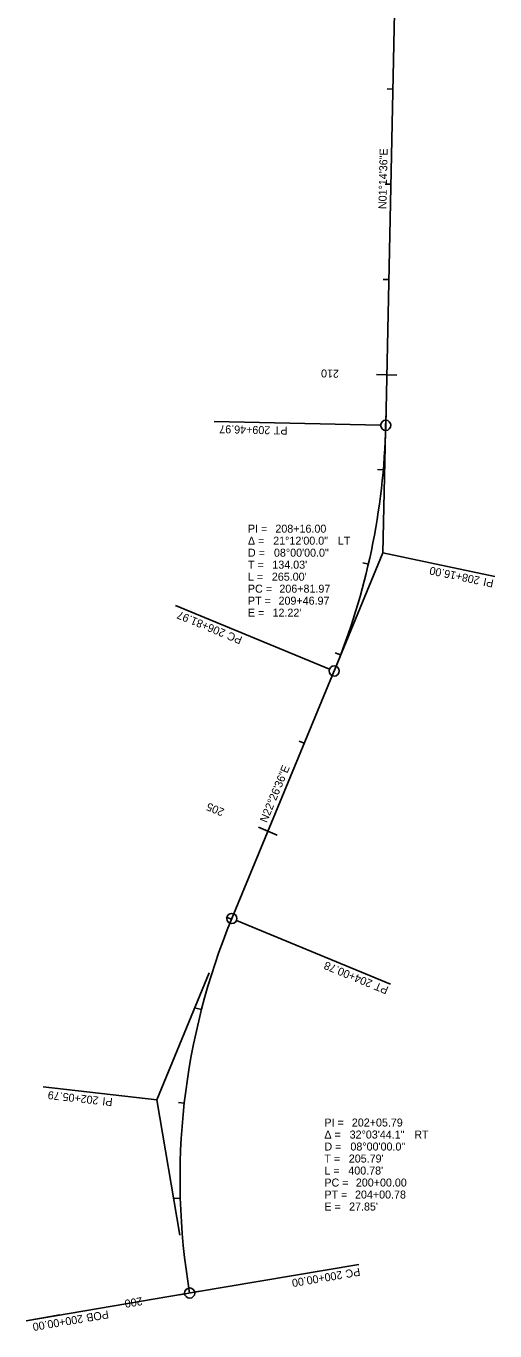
# Model space of a CAD drawing. Extents: x 1145421 to 1155673, y 2015317 to 2021442.
# Drawn here: x 1151300 to 1151792, y 2018531 to 2019901 of the extents above; entities that cross this region are included whole.
import ezdxf

# ---------------------------------------------------------------- set-up
doc = ezdxf.new("R2010")
doc.units = 0
for name, color, linetype in [('Default', 7, 'Continuous'), ('EX_CONTOUR_ANNOT_MINOR', 7, 'Continuous'), ('EX_TERRAIN', 7, 'Continuous')]:
    doc.layers.add(name, color=color, linetype=linetype)

msp = doc.modelspace()

# ---------------------------------------------------------------- linework, layer by layer
at = {"layer": 'Default'}
for p, q in [((1151677.3, 2019481.5), (1151688.6, 2020003.4)), ((1151515.9, 2018963.7), (1151623.2, 2019223.6)), ((1151515.9, 2018963.7), (1151623.2, 2019223.6))]:
    msp.add_line(p, q, dxfattribs=at)
msp.add_arc((1150961.3, 2019497), 716.2, 337.5565, 358.7565, dxfattribs=at)
at = {"layer": 'EX_CONTOUR_ANNOT_MINOR'}
for p, q in [((1151679, 2019834.6), (1151684.9, 2019834.4)), ((1151676.8, 2019734.6), (1151682.8, 2019734.5)), ((1151674.6, 2019634.6), (1151680.6, 2019634.5)), ((1151667.8, 2019534.7), (1151689, 2019534.3)), ((1151674.4, 2019347.5), (1151677.5, 2019491.5)), ((1151671.9, 2019481.6), (1151497.3, 2019485.4)), ((1151497.3, 2019485.4), (1151497.3, 2019485.4)), ((1151677.3, 2019481.5), (1151677.3, 2019481.5)), ((1151668.8, 2019435.1), (1151674.7, 2019434.6)), ((1151674.4, 2019347.5), (1151619.4, 2019214.4)), ((1151674.4, 2019347.5), (1151791.8, 2019322.9)), ((1151653.3, 2019337.3), (1151659.1, 2019335.9)), ((1151791.8, 2019322.9), (1151791.8, 2019322.9)), ((1151618.3, 2019225.6), (1151456.8, 2019292.3)), ((1151456.8, 2019292.3), (1151456.8, 2019292.3)), ((1151624.3, 2019242.5), (1151629.9, 2019240.4)), ((1151623.2, 2019223.6), (1151623.2, 2019223.6)), ((1151586.4, 2019150.1), (1151591.9, 2019147.8)), ((1151543.9, 2019059.5), (1151563.5, 2019051.4)), ((1151510, 2018965.3), (1151515.6, 2018963)), ((1151515.9, 2018963.7), (1151515.9, 2018963.7)), ((1151520.8, 2018961.7), (1151682.2, 2018895)), ((1151437.3, 2018773.5), (1151492.3, 2018906.6)), ((1151682.2, 2018895), (1151682.2, 2018895)), ((1151478.2, 2018869.7), (1151484.1, 2018868.2)), ((1151437.3, 2018773.5), (1151318, 2018786.9)), ((1151318, 2018786.9), (1151318, 2018786.9)), ((1151437.3, 2018773.5), (1151461.4, 2018631.5)), ((1151460.1, 2018770.6), (1151466, 2018769.9)), ((1151455.9, 2018669.9), (1151461.9, 2018670.1)), ((1151476.9, 2018571.5), (1151649.2, 2018600.7)), ((1151649.2, 2018600.7), (1151649.2, 2018600.7)), ((1151461.2, 2018568.8), (1151482.1, 2018572.4)), ((1151466.4, 2018569.7), (1151300.1, 2018541.5)), ((1151471.7, 2018570.6), (1151471.7, 2018570.6)), ((1151300.1, 2018541.5), (1151335.6, 2018547.6))]:
    msp.add_line(p, q, dxfattribs=at)
for centre in [(1151677.3, 2019481.5), (1151623.2, 2019223.6), (1151515.9, 2018963.7), (1151471.7, 2018570.6)]:
    msp.add_circle(centre, 5.34, dxfattribs=at)
at = {"layer": 'EX_TERRAIN'}
for p, q in [((1151677.3, 2019481.5), (1151688.6, 2020003.4)), ((1151515.9, 2018963.7), (1151623.2, 2019223.6))]:
    msp.add_line(p, q, dxfattribs=at)
for centre, start, end in [((1150961.3, 2019497), 337.5565, 358.7565), ((1152177.8, 2018690.3), 157.5565, 189.6188)]:
    msp.add_arc(centre, 716.2, start, end, dxfattribs=at)

# ---------------------------------------------------------------- texts
at = {"layer": 'EX_CONTOUR_ANNOT_MINOR'}
for s, rotation, p in [('N01°14\'36"E', 88.7565, (1151678, 2019708.4)), ('210', 178.7565, (1151628.3, 2019539.8)), ('209+46.97', 178.7565, (1151556.3, 2019480.5)), ('PT', 178.7565, (1151574.4, 2019480.1)), ('208+16.00', 168.1565, (1151776.6, 2019322.4)), ('PI ', 168.1565, (1151791.1, 2019319.3)), ('206+81.97', 157.5565, (1151510, 2019266.5)), ('PC', 157.5565, (1151527.6, 2019259.2)), ('N22°26\'36"E', 67.5565, (1151552.6, 2019063.7)), ('205', 157.5565, (1151508.8, 2019078.5)), ('204+00.78', 157.5565, (1151664.1, 2018898.6)), ('PT', 157.5565, (1151680.9, 2018891.7)), ('202+05.79', 173.5877, (1151376.5, 2018776.7)), ('PI ', 173.5877, (1151391.2, 2018775.1)), ('200+00.00', 189.6188, (1151631, 2018594)), ('PC', 189.6188, (1151649.8, 2018597.2)), ('200', 189.6188, (1151421.4, 2018566.4)), ('200+00.00', 189.6188, (1151359.1, 2018547.9)), ('POB ', 189.6188, (1151386, 2018552.5))]:
    msp.add_text(s, height=8.4, rotation=rotation, dxfattribs=at).set_placement(p)
for s, p in [('PI = ', (1151532.8, 2019368.8)), ('208+16.00', (1151561.6, 2019368.8)), ('Δ = ', (1151532.8, 2019356.2)), ('D = ', (1151532.8, 2019343.6)), ('21°12\'00.0"', (1151559.3, 2019356.2)), ('08°00\'00.0"', (1151560.1, 2019343.6)), (' LT', (1151624, 2019356.2)), ('T = ', (1151532.8, 2019331)), ("134.03'", (1151558.4, 2019331)), ('L = ', (1151532.8, 2019318.4)), ("265.00'", (1151557.9, 2019318.4)), ('PC = ', (1151532.8, 2019305.8)), ('206+81.97', (1151565.8, 2019305.8)), ('PT = ', (1151532.8, 2019293.2)), ('209+46.97', (1151564.9, 2019293.2)), ('E = ', (1151532.8, 2019280.6)), ("12.22'", (1151558.6, 2019280.6)), ('PI = ', (1151613, 2018745.4)), ('202+05.79', (1151641.8, 2018745.4)), ('Δ = ', (1151613, 2018732.8)), ('32°03\'44.1"', (1151639.5, 2018732.8)), (' RT', (1151704.2, 2018732.8)), ('D = ', (1151613, 2018720.2)), ('08°00\'00.0"', (1151640.3, 2018720.2)), ('T = ', (1151613, 2018707.6)), ("205.79'", (1151638.6, 2018707.6)), ('L = ', (1151613, 2018695)), ("400.78'", (1151638.1, 2018695)), ('PC = ', (1151613, 2018682.4)), ('200+00.00', (1151646, 2018682.4)), ('PT = ', (1151613, 2018669.8)), ('204+00.78', (1151645.1, 2018669.8)), ('E = ', (1151613, 2018657.2)), ("27.85'", (1151638.9, 2018657.2))]:
    msp.add_text(s, height=8.4, dxfattribs=at).set_placement(p)

doc.saveas('drawing.dxf')
